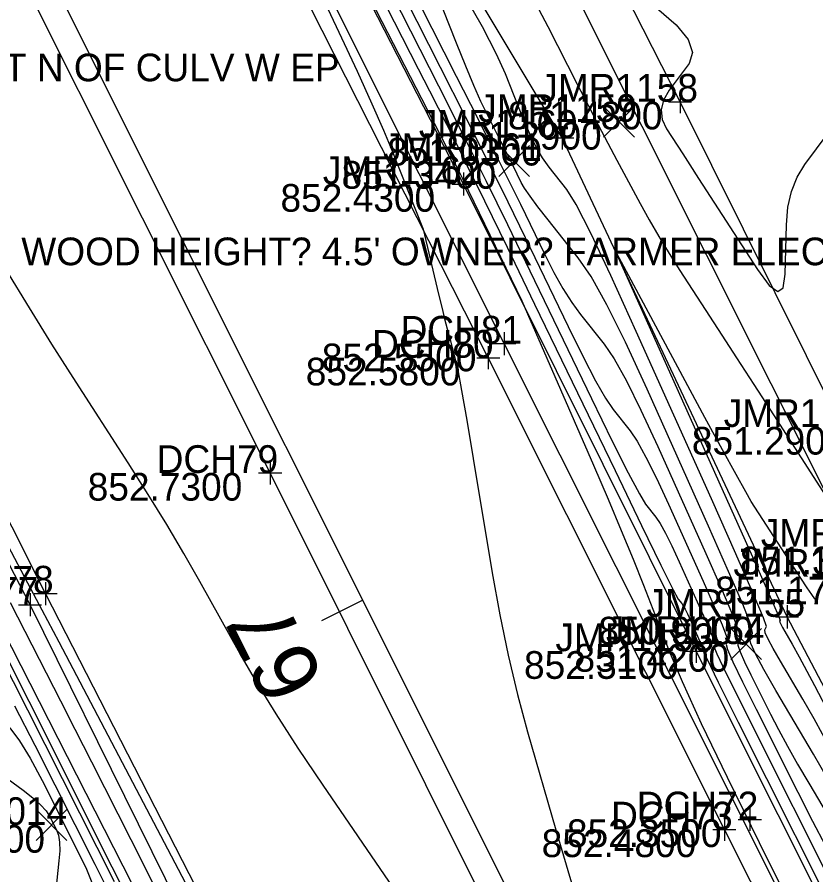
# Model space of a CAD drawing. Extents: x 1654928 to 1810050, y 486881 to 626330.
# Drawn here: x 1801345.62 to 1801380.19, y 489953.22 to 489990.37 of the extents above; entities that cross this region are included whole.
import ezdxf

# ---------------------------------------------------------------- set-up
doc = ezdxf.new("R2010")
doc.units = 0
for name, color, linetype in [('DR_X_Ditch', 7, 'Continuous'), ('DT_X_Contour_Major', 7, 'Continuous'), ('DT_X_Contour_Minor', 7, 'Continuous'), ('PV_X_EOP', 7, 'Continuous'), ('PV_X_Shoulder', 7, 'Continuous'), ('RD_X_Fence', 7, 'Continuous'), ('RW_X_Esmt_SH', 7, 'Continuous'), ('SV_X_Break_Lines', 7, 'Continuous'), ('SV_X_Center_of_Pavt', 7, 'Continuous'), ('SV_X_CL_Survey_20', 7, 'Continuous'), ('SV_X_Random_Point', 7, 'Continuous'), ('SV_X_Shot_Marker', 7, 'Continuous'), ('SV_X_Text_Comment', 7, 'Continuous'), ('SV_X_Text_Elevation', 7, 'Continuous'), ('SV_X_Text_Name', 7, 'Continuous')]:
    doc.layers.add(name, color=color, linetype=linetype)

msp = doc.modelspace()

# ---------------------------------------------------------------- linework, layer by layer
at = {"layer": 'DR_X_Ditch'}
msp.add_lwpolyline([(1801398.424, 489926.897), (1801390.073, 489943.195), (1801378.941, 489964.397), (1801369.209, 489985.145), (1801358.751, 490002.608)], dxfattribs=at)
at = {"layer": 'DT_X_Contour_Major'}
for points in [[(1801361.429, 489992.171), (1801364.253, 489986.601), (1801365.058, 489985.001), (1801365.919, 489983.265), (1801366.836, 489981.393), (1801367.81, 489979.384), (1801370.482, 489973.847), (1801371.379, 489972.004), (1801372.068, 489970.628), (1801372.548, 489969.718), (1801372.819, 489969.275), (1801373.264, 489968.715), (1801373.453, 489968.436), (1801373.685, 489968.02), (1801373.96, 489967.467), (1801374.279, 489966.777), (1801375.186, 489964.754), (1801375.482, 489964.086), (1801375.689, 489963.599), (1801375.806, 489963.294), (1801375.834, 489963.171), (1801375.791, 489963.083), (1801375.905, 489962.798), (1801376.282, 489962.006), (1801376.921, 489960.709), (1801377.822, 489958.907), (1801380.575, 489953.425)], [(1801380.212, 489965.109), (1801380.146, 489965.179), (1801380.014, 489965.363), (1801379.813, 489965.659), (1801379.546, 489966.069), (1801377.396, 489969.399), (1801377.151, 489969.812), (1801376.734, 489970.555), (1801376.147, 489971.629), (1801375.39, 489973.033), (1801371.455, 489980.357), (1801376.499, 489969.111), (1801377.444, 489967), (1801378.116, 489965.487), (1801378.516, 489964.572), (1801378.643, 489964.255), (1801378.619, 489964.207), (1801378.626, 489964.165), (1801378.666, 489964.076), (1801378.739, 489963.94), (1801378.845, 489963.757), (1801379.17, 489963.207), (1801379.47, 489962.657), (1801380.126, 489961.418), (1801381.139, 489959.492)], [(1801344.553, 489964.664), (1801350.197, 489953.606), (1801351.808, 489950.439), (1801352.274, 489949.518), (1801354.342, 489945.414), (1801359.53, 489935.147), (1801360.682, 489932.876), (1801361.734, 489930.824), (1801362.685, 489928.991), (1801363.535, 489927.377), (1801365.669, 489923.365), (1801366.482, 489921.817), (1801367.323, 489920.181), (1801368.19, 489918.458), (1801369.084, 489916.647), (1801372.39, 489909.892), (1801374.021, 489906.547), (1801376.699, 489901.037), (1801377.442, 489899.52), (1801377.866, 489898.669)]]:
    msp.add_lwpolyline(points, dxfattribs=at)
at = {"layer": 'DT_X_Contour_Minor'}
for points in [[(1801356.249, 490000.21), (1801363.117, 489986.849), (1801364.75, 489983.671), (1801364.894, 489983.386), (1801365.16, 489982.844), (1801367.457, 489978.086), (1801370.559, 489970.96), (1801371.193, 489969.49), (1801371.765, 489968.134), (1801372.276, 489966.893), (1801372.724, 489965.767), (1801373.838, 489962.915), (1801374.395, 489961.594), (1801375.231, 489959.771), (1801376.346, 489957.446), (1801377.74, 489954.618), (1801381.828, 489946.407)], [(1801357.256, 489994.579), (1801359.543, 489989.722), (1801360.329, 489988.036), (1801360.974, 489986.623), (1801361.476, 489985.481), (1801361.837, 489984.612), (1801363.187, 489981.189), (1801363.858, 489978.378), (1801363.995, 489977.81), (1801364.118, 489977.308), (1801364.229, 489976.875), (1801364.326, 489976.508), (1801364.568, 489975.62), (1801364.685, 489975.098), (1801364.857, 489974.195), (1801365.082, 489972.912), (1801365.361, 489971.248), (1801366.178, 489966.306), (1801366.503, 489964.486), (1801366.867, 489962.73), (1801367.269, 489961.039), (1801367.71, 489959.413), (1801368.936, 489955.164), (1801369.449, 489953.407), (1801370.068, 489951.322)], [(1801360.9, 489994.194), (1801363.932, 489988.209), (1801365.015, 489986.064), (1801365.988, 489984.118), (1801366.851, 489982.372), (1801367.604, 489980.825), (1801369.466, 489976.966), (1801370.112, 489975.657), (1801370.651, 489974.623), (1801371.084, 489973.864), (1801371.412, 489973.381), (1801372.144, 489972.46), (1801372.454, 489972.002), (1801372.836, 489971.318), (1801373.289, 489970.408), (1801373.813, 489969.273), (1801375.306, 489965.944), (1801375.793, 489964.845), (1801376.132, 489964.045), (1801376.326, 489963.543), (1801376.372, 489963.339), (1801376.3, 489963.196), (1801376.361, 489962.98), (1801376.598, 489962.441), (1801377.011, 489961.579), (1801377.599, 489960.394), (1801379.402, 489956.803), (1801380.04, 489955.547), (1801380.6, 489954.473)], [(1801361.977, 489993.042), (1801364.624, 489987.82), (1801365.542, 489986.004), (1801366.31, 489984.473), (1801366.929, 489983.227), (1801367.398, 489982.267), (1801368.451, 489980.085), (1801368.844, 489979.309), (1801369.234, 489978.618), (1801369.621, 489978.011), (1801370.005, 489977.488), (1801371.024, 489976.205), (1801371.456, 489975.567), (1801371.987, 489974.615), (1801372.617, 489973.349), (1801373.347, 489971.768), (1801375.426, 489967.134), (1801376.103, 489965.604), (1801376.576, 489964.49), (1801376.845, 489963.791), (1801376.91, 489963.508), (1801376.81, 489963.308), (1801376.817, 489963.162), (1801376.914, 489962.876), (1801377.1, 489962.449), (1801377.376, 489961.881), (1801378.23, 489960.18), (1801378.574, 489959.515), (1801378.964, 489958.794), (1801379.401, 489958.018), (1801379.884, 489957.187), (1801381.236, 489954.897)], [(1801380.754, 489957.288), (1801380.086, 489958.449), (1801378.461, 489961.201), (1801377.934, 489962.116), (1801377.57, 489962.795), (1801377.37, 489963.238), (1801377.333, 489963.447), (1801377.453, 489963.688), (1801377.368, 489964.046), (1801377.021, 489964.938), (1801376.414, 489966.364), (1801375.545, 489968.324), (1801372.881, 489974.263), (1801371.946, 489976.289), (1801371.138, 489977.912), (1801370.457, 489979.133), (1801369.904, 489979.95), (1801368.597, 489981.594), (1801368.157, 489982.157), (1801367.817, 489982.613), (1801367.576, 489982.962), (1801367.435, 489983.204), (1801367.084, 489983.929), (1801366.941, 489984.217), (1801366.764, 489984.57), (1801366.552, 489984.989), (1801365.941, 489986.194), (1801365.688, 489986.724), (1801365.386, 489987.409), (1801365.035, 489988.25), (1801364.636, 489989.246), (1801363.505, 489992.109)], [(1801380.833, 489958.644), (1801380.112, 489959.972), (1801379.628, 489960.828), (1801378.653, 489962.479), (1801378.337, 489963.028), (1801378.118, 489963.435), (1801377.998, 489963.702), (1801377.976, 489963.827), (1801378.048, 489963.972), (1801377.919, 489964.359), (1801377.479, 489965.411), (1801376.728, 489967.13), (1801375.665, 489969.514), (1801372.416, 489976.759), (1801371.313, 489979.181), (1801370.444, 489981.014), (1801369.809, 489982.258), (1801369.406, 489982.913), (1801368.642, 489983.873), (1801368.356, 489984.277), (1801368.072, 489984.769), (1801367.79, 489985.348), (1801367.508, 489986.015), (1801366.76, 489987.91), (1801366.369, 489988.775), (1801365.756, 489989.947), (1801364.921, 489991.428)], [(1801361.588, 489990.854), (1801362.981, 489988.133), (1801363.466, 489987.179), (1801364.574, 489984.993), (1801365.1, 489983.938), (1801365.849, 489982.411), (1801366.821, 489980.413), (1801368.015, 489977.943), (1801371.497, 489970.728), (1801372.647, 489968.352), (1801373.485, 489966.633), (1801374.012, 489965.572), (1801374.227, 489965.168), (1801374.385, 489964.969), (1801374.451, 489964.871), (1801374.534, 489964.723), (1801374.631, 489964.527), (1801374.745, 489964.282), (1801375.171, 489963.327), (1801375.245, 489963.154), (1801375.286, 489963.046), (1801375.296, 489963.002), (1801375.281, 489962.971), (1801375.449, 489962.616), (1801375.966, 489961.572), (1801376.832, 489959.84), (1801381.747, 489950.048)], [(1801368.069, 489990.955), (1801368.581, 489989.965), (1801369.859, 489987.469), (1801370.326, 489986.561), (1801370.768, 489985.711), (1801371.184, 489984.919), (1801371.576, 489984.184), (1801372.588, 489982.301), (1801372.98, 489981.59), (1801373.397, 489980.87), (1801373.839, 489980.141), (1801374.307, 489979.403), (1801375.587, 489977.423), (1801376.119, 489976.599), (1801376.758, 489975.611), (1801377.502, 489974.458), (1801378.351, 489973.142), (1801380.758, 489969.414)], [(1801373.285, 489990.77), (1801374.144, 489990.041), (1801374.666, 489989.398), (1801374.85, 489988.838), (1801374.698, 489988.363), (1801373.841, 489987.208), (1801373.593, 489986.779), (1801373.491, 489986.356), (1801373.535, 489985.939), (1801373.725, 489985.529), (1801374.425, 489984.446), (1801374.728, 489983.978), (1801375.109, 489983.387), (1801377.659, 489979.437), (1801378.169, 489978.75), (1801378.54, 489978.488), (1801378.77, 489978.651), (1801378.861, 489979.239), (1801378.916, 489981.372), (1801378.981, 489982.136), (1801379.135, 489982.827), (1801379.378, 489983.445), (1801379.711, 489983.99), (1801380.717, 489985.346)], [(1801373.135, 489941.22), (1801375.755, 489932.629), (1801367.636, 489944.338), (1801365.972, 489946.74), (1801364.459, 489948.931), (1801363.097, 489950.911), (1801361.886, 489952.678), (1801358.859, 489957.108), (1801357.784, 489958.709), (1801356.828, 489960.189), (1801355.992, 489961.549), (1801355.275, 489962.787), (1801353.523, 489965.93), (1801352.836, 489967.135), (1801352.091, 489968.392), (1801351.286, 489969.701), (1801350.423, 489971.063), (1801348.041, 489974.763), (1801347.122, 489976.211), (1801346.15, 489977.776), (1801345.125, 489979.461)], [(1801344.35, 489969.1), (1801346.064, 489965.873), (1801346.684, 489964.701), (1801347.414, 489963.315), (1801352.289, 489954.042), (1801355.202, 489948.481), (1801355.772, 489947.399), (1801356.299, 489946.411), (1801356.782, 489945.517), (1801357.222, 489944.718), (1801359.175, 489941.208), (1801368.351, 489928.2), (1801370.106, 489925.653), (1801371.437, 489923.588), (1801372.345, 489922.005), (1801372.83, 489920.904), (1801373.559, 489918.61), (1801373.927, 489917.536)], [(1801345.314, 489965.023), (1801345.953, 489963.778), (1801347.496, 489960.755), (1801348.119, 489959.53), (1801348.833, 489958.122), (1801350.531, 489954.757), (1801354.681, 489946.516), (1801357.125, 489941.676), (1801357.735, 489940.489), (1801358.616, 489938.801), (1801359.77, 489936.614), (1801361.196, 489933.926), (1801366.739, 489923.501), (1801367.746, 489921.602), (1801368.383, 489920.395), (1801368.651, 489919.88), (1801369.129, 489918.901), (1801375.971, 489904.816)], [(1801344.815, 489962.818), (1801346.058, 489960.371), (1801349.818, 489952.937)], [(1801345.499, 489960.543), (1801346.379, 489958.835), (1801348.982, 489953.689), (1801349.833, 489951.976)], [(1801345.303, 489959.59), (1801345.717, 489959.032), (1801346.183, 489958.269), (1801346.7, 489957.3), (1801348.146, 489954.44), (1801348.616, 489953.461), (1801348.941, 489952.666)], [(1801344.623, 489957.802), (1801345.869, 489956.882), (1801346.291, 489956.554), (1801346.624, 489956.258), (1801346.867, 489955.994), (1801347.02, 489955.764), (1801347.309, 489955.192), (1801347.398, 489954.945), (1801347.447, 489954.635), (1801347.456, 489954.261), (1801347.426, 489953.823), (1801347.293, 489952.57)]]:
    msp.add_lwpolyline(points, dxfattribs=at)
at = {"layer": 'PV_X_EOP'}
for points in [[(1801533.684, 489642.188), (1801522.484, 489664.508), (1801511.881, 489685.341), (1801500.299, 489708.684), (1801491.104, 489726.659), (1801480.832, 489747.383), (1801466.882, 489774.659), (1801456.506, 489795.715), (1801444.637, 489819.009), (1801433.258, 489841.444), (1801422.029, 489863.995), (1801410.905, 489885.928), (1801399.817, 489908.089), (1801388.576, 489930.656), (1801376.228, 489955.188), (1801366.008, 489975.62), (1801354.725, 489997.894)], [(1801513.785, 489634.043), (1801503.26, 489654.965), (1801492.692, 489675.84), (1801481.803, 489697.704), (1801472.078, 489717.629), (1801460.782, 489739.414), (1801448.005, 489764.97), (1801436.553, 489786.89), (1801425.237, 489809.697), (1801414.345, 489830.894), (1801402.21, 489854.742), (1801391.781, 489876.056), (1801380.008, 489899.32), (1801369.395, 489920.807), (1801356.62, 489946.308), (1801346.845, 489965.404), (1801335.257, 489988.444)]]:
    msp.add_lwpolyline(points, dxfattribs=at)
at = {"layer": 'PV_X_Shoulder'}
for points in [[(1801534.471, 489642.456), (1801522.963, 489664.954), (1801512.6, 489685.485), (1801500.973, 489709.112), (1801491.766, 489727.019), (1801481.526, 489747.768), (1801467.484, 489775.07), (1801457.116, 489796.092), (1801445.57, 489819.398), (1801434.029, 489841.927), (1801422.682, 489864.343), (1801411.885, 489886.25), (1801400.664, 489908.455), (1801366.703, 489976.232), (1801355.676, 489998.276)], [(1801513.053, 489633.484), (1801502.425, 489654.401), (1801492.155, 489675.438), (1801481.048, 489697.245), (1801471.095, 489717.056), (1801459.974, 489738.844), (1801446.996, 489764.517), (1801435.938, 489786.184), (1801424.33, 489809.156), (1801413.386, 489830.353), (1801401.606, 489854.259), (1801390.811, 489875.349), (1801379.301, 489898.985), (1801368.607, 489920.204), (1801355.561, 489945.921), (1801346.174, 489964.922), (1801334.144, 489988.199)]]:
    msp.add_lwpolyline(points, dxfattribs=at)
at = {"layer": 'RD_X_Fence'}
msp.add_lwpolyline([(1801406.8, 489921.921), (1801396.014, 489944.401), (1801383.891, 489967.432), (1801374.312, 489986.711), (1801364.337, 490006.337)], dxfattribs=at)
at = {"layer": 'RW_X_Esmt_SH'}
msp.add_line((1801569.151, 489592.806), (1801345.762, 490039.449), dxfattribs=at)
at = {"layer": 'SV_X_Break_Lines'}
for points in [[(1801445.791, 489822.136), (1801441.193, 489830.46), (1801435.211, 489842.68), (1801424.275, 489864.659), (1801412.811, 489886.984), (1801408.709, 489897.161), (1801400.001, 489913.183), (1801395.188, 489923.674), (1801385.653, 489941.642), (1801375.001, 489962.91), (1801364.942, 489983.144), (1801355.514, 490001.536)], [(1801419.479, 489816.264), (1801413.606, 489827.582), (1801399.229, 489854.903), (1801388.205, 489875.792), (1801377.391, 489897.446), (1801365.991, 489920.501), (1801353.319, 489946.375), (1801342.526, 489967.898), (1801332.595, 489987.823)]]:
    msp.add_lwpolyline(points, dxfattribs=at)
at = {"layer": 'SV_X_Center_of_Pavt'}
msp.add_lwpolyline([(1801523.585, 489638.313), (1801512.853, 489659.481), (1801502.374, 489680.412), (1801490.819, 489703.952), (1801481.428, 489721.68), (1801470.803, 489742.834), (1801457.335, 489769.613), (1801446.389, 489792.464), (1801435.307, 489813.792), (1801423.54, 489836.522), (1801412.234, 489859.298), (1801401.202, 489881.345), (1801390.005, 489903.67), (1801378.784, 489926.715), (1801366.669, 489950.371), (1801356.567, 489970.63), (1801345.517, 489992.708)], dxfattribs=at)
at = {"layer": 'SV_X_CL_Survey_20'}
for p, q in [((1802886.975, 486913.246), (1801128.538, 490429.055)), ((1802886.975, 486913.246), (1801128.538, 490429.055)), ((1801360.578, 489965.115), (1801358.789, 489964.22))]:
    msp.add_line(p, q, dxfattribs=at)
at = {"layer": 'SV_X_Random_Point'}
for p, q in [((1801371.002, 489985.168), (1801372.336, 489986.503)), ((1801371.002, 489986.503), (1801372.336, 489985.168)), ((1801366.464, 489983.472), (1801367.797, 489984.807)), ((1801366.464, 489984.807), (1801367.797, 489983.472)), ((1801376.508, 489962.553), (1801377.842, 489963.888)), ((1801376.508, 489963.888), (1801377.842, 489962.553)), ((1801346.434, 489954.712), (1801347.767, 489956.047)), ((1801346.434, 489956.047), (1801347.767, 489954.712))]:
    msp.add_line(p, q, dxfattribs=at)
at = {"layer": 'SV_X_Shot_Marker'}
for p, q in [((1801374.312, 489987.211), (1801374.312, 489986.211)), ((1801373.812, 489986.711), (1801374.812, 489986.711)), ((1801374.312, 489986.711), (1801374.312, 489986.711)), ((1801369.209, 489985.645), (1801369.209, 489984.645)), ((1801368.709, 489985.145), (1801369.709, 489985.145)), ((1801369.209, 489985.145), (1801369.209, 489985.145)), ((1801364.942, 489983.644), (1801364.942, 489982.644)), ((1801364.442, 489983.144), (1801365.442, 489983.144)), ((1801364.942, 489983.144), (1801364.942, 489983.144)), ((1801366.703, 489976.732), (1801366.703, 489975.732)), ((1801366.008, 489976.12), (1801366.008, 489975.12)), ((1801366.203, 489976.232), (1801367.203, 489976.232)), ((1801366.703, 489976.232), (1801366.703, 489976.232)), ((1801365.508, 489975.62), (1801366.508, 489975.62)), ((1801366.008, 489975.62), (1801366.008, 489975.62)), ((1801356.567, 489971.13), (1801356.567, 489970.13)), ((1801356.067, 489970.63), (1801357.067, 489970.63)), ((1801356.567, 489970.63), (1801356.567, 489970.63)), ((1801346.845, 489965.904), (1801346.845, 489964.904)), ((1801346.174, 489965.422), (1801346.174, 489964.422)), ((1801346.345, 489965.404), (1801347.345, 489965.404)), ((1801346.845, 489965.404), (1801346.845, 489965.404)), ((1801345.674, 489964.922), (1801346.674, 489964.922)), ((1801346.174, 489964.922), (1801346.174, 489964.922)), ((1801378.941, 489964.897), (1801378.941, 489963.897)), ((1801378.441, 489964.397), (1801379.441, 489964.397)), ((1801378.941, 489964.397), (1801378.941, 489964.397)), ((1801375.001, 489963.41), (1801375.001, 489962.41)), ((1801374.501, 489962.91), (1801375.501, 489962.91)), ((1801375.001, 489962.91), (1801375.001, 489962.91)), ((1801377.331, 489956.124), (1801377.331, 489955.124)), ((1801376.228, 489955.688), (1801376.228, 489954.688)), ((1801376.831, 489955.624), (1801377.831, 489955.624)), ((1801377.331, 489955.624), (1801377.331, 489955.624)), ((1801375.728, 489955.188), (1801376.728, 489955.188)), ((1801376.228, 489955.188), (1801376.228, 489955.188))]:
    msp.add_line(p, q, dxfattribs=at)

# ---------------------------------------------------------------- texts
at = {"layer": 'SV_X_CL_Survey_20'}
msp.add_text('67', height=2.8, rotation=116.572, dxfattribs=at).set_placement((1801358.955, 489961.654))
at = {"layer": 'SV_X_Text_Comment'}
for s, p in [('NOTE 1 200 FT N OF CULV W EP', (1801334.696, 489987.594)), ("BL*FEN FENDAT TYPE? WOOD HEIGHT? 4.5' OWNER? FARMER ELECTRIC", (1801327.157, 489979.625))]:
    msp.add_text(s, height=1.2, dxfattribs=at).set_placement(p)
at = {"layer": 'SV_X_Text_Elevation'}
for s, p in [('851.4800', (1801366.858, 489985.511)), ('851.2900', (1801364.224, 489984.635)), ('851.0300', (1801361.632, 489983.945)), ('851.3400', (1801359.658, 489982.94)), ('852.4300', (1801357.015, 489981.944)), ('852.5500', (1801358.804, 489975.032)), ('852.5800', (1801358.109, 489974.42)), ('851.2900', (1801374.821, 489971.423)), ('852.7300', (1801348.668, 489969.43)), ('851.3100', (1801376.9, 489966.232)), ('851.1700', (1801375.826, 489964.942)), ('850.9000', (1801370.777, 489963.197)), ('852.3100', (1801367.556, 489961.71)), ('851.4200', (1801369.74, 489962.02)), ('852.3500', (1801369.413, 489954.424)), ('851.1500', (1801340.129, 489954.18)), ('852.4800', (1801368.32, 489953.988))]:
    msp.add_text(s, height=1.2, dxfattribs=at).set_placement(p)
at = {"layer": 'SV_X_Text_Name'}
for s, p in [('JMR1158', (1801368.219, 489986.711)), ('JMR1159', (1801365.576, 489985.835)), ('JMR1160', (1801363.003, 489985.145)), ('JMR1161', (1801361.462, 489984.14)), ('JMR1162', (1801358.849, 489983.144)), ('DCH81', (1801362.214, 489976.232)), ('DCH80', (1801360.981, 489975.62)), ('JMR1175', (1801376.201, 489972.623)), ('DCH79', (1801351.654, 489970.63)), ('JMR1157', (1801377.807, 489967.432)), ('JMR1156', (1801376.62, 489966.142)), ('DCH78', (1801341.932, 489965.404)), ('DCH77', (1801341.27, 489964.922)), ('JMR1155', (1801372.857, 489964.397)), ('JMR1154', (1801371.101, 489963.22)), ('JMR1153', (1801368.917, 489962.91)), ('JMR1014', (1801340.913, 489955.38)), ('DCH72', (1801372.437, 489955.624)), ('DCH73', (1801371.325, 489955.188))]:
    msp.add_text(s, height=1.2, dxfattribs=at).set_placement(p)

doc.saveas('drawing.dxf')
